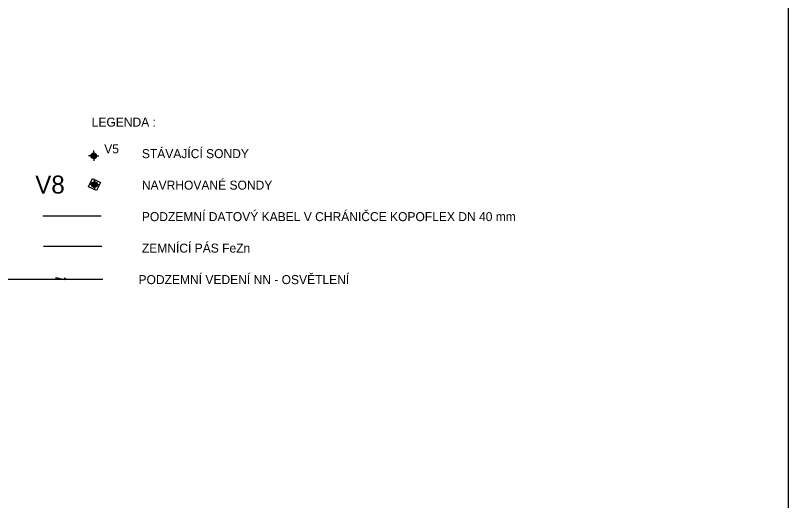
# Model space of a CAD drawing. Extents: x -517788 to -517166, y -1177087 to -1176790.
# Drawn here: x -517251.8 to -517165.9, y -1176994 to -1176940.1 of the extents above; entities that cross this region are included whole.
import ezdxf

# ---------------------------------------------------------------- set-up
doc = ezdxf.new("R2010")
doc.units = 0
doc.layers.add('mapove znacky', color=7, linetype='Continuous')
doc.layers.add('označení lomového bodu', color=7, linetype='Continuous')

msp = doc.modelspace()

# ---------------------------------------------------------------- linework, layer by layer
at = {"layer": 'mapove znacky'}
for p, q in [((-517243.399, -1176955.672), (-517243.649, -1176955.672)), ((-517243.397, -1176955.711), (-517242.898, -1176955.423)), ((-517243.396, -1176955.63), (-517242.969, -1176955.383)), ((-517243.379, -1176955.782), (-517242.846, -1176955.474)), ((-517243.365, -1176955.531), (-517243.07, -1176955.361)), ((-517243.347, -1176955.844), (-517242.808, -1176955.533)), ((-517243.302, -1176955.899), (-517242.783, -1176955.599)), ((-517243.241, -1176955.944), (-517242.774, -1176955.675)), ((-517243.157, -1176955.977), (-517242.788, -1176955.764)), ((-517243.087, -1176955.36), (-517243.087, -1176955.11)), ((-517242.774, -1176955.672), (-517242.524, -1176955.672)), ((-517243.087, -1176955.985), (-517243.087, -1176956.235)), ((-517243.017, -1176955.977), (-517242.858, -1176955.885)), ((-517243.003, -1176958.566), (-517243.003, -1176958.316)), ((-517243.315, -1176958.879), (-517243.565, -1176958.879)), ((-517243.313, -1176958.917), (-517242.814, -1176958.63)), ((-517243.312, -1176958.836), (-517242.885, -1176958.59)), ((-517243.295, -1176958.988), (-517242.762, -1176958.68)), ((-517243.281, -1176958.738), (-517242.986, -1176958.567)), ((-517243.263, -1176959.051), (-517242.724, -1176958.739)), ((-517243.218, -1176959.105), (-517242.699, -1176958.806)), ((-517243.157, -1176959.151), (-517242.69, -1176958.882)), ((-517243.073, -1176959.183), (-517242.704, -1176958.97)), ((-517243.003, -1176959.191), (-517243.003, -1176959.441)), ((-517242.933, -1176959.183), (-517242.774, -1176959.092)), ((-517242.69, -1176958.879), (-517242.44, -1176958.879))]:
    msp.add_line(p, q, dxfattribs=at)
for centre in [(-517243.087, -1176955.672), (-517243.003, -1176958.879)]:
    msp.add_circle(centre, 0.312, dxfattribs=at)
at = {"layer": 'označení lomového bodu'}
for p, q in [((-517242.277, -1176962.393), (-517248.75, -1176962.393)), ((-517242.174, -1176965.76), (-517248.647, -1176965.76)), ((-517252.874, -1176969.38), (-517242.088, -1176969.38)), ((-517247.253, -1176969.38), (-517247.253, -1176969.191)), ((-517247.253, -1176969.191), (-517246.565, -1176969.38)), ((-517246.203, -1176969.38), (-517246.378, -1176969.296)), ((-517246.203, -1176969.38), (-517246.378, -1176969.464))]:
    msp.add_line(p, q, dxfattribs=at)
for points in [[(-517375.912, -1176938.722), (-517375.912, -1177087.222), (-517165.912, -1177087.222), (-517165.912, -1176938.722)], [(-517248.647, -1176969.38), (-517248.646, -1176969.38)], [(-517248.121, -1176969.38), (-517247.253, -1176969.38)], [(-517246.565, -1176969.38), (-517246.203, -1176969.38)], [(-517245.937, -1176969.38), (-517245.153, -1176969.38)], [(-517244.67, -1176969.38), (-517243.76, -1176969.38)], [(-517243.235, -1176969.38), (-517242.318, -1176969.38)]]:
    msp.add_lwpolyline(points, dxfattribs=at)
msp.add_lwpolyline([(-517242.777, -1176959.536), (-517243.658, -1176959.113), (-517243.229, -1176958.221), (-517242.348, -1176958.644)], close=True, dxfattribs=at)

# ---------------------------------------------------------------- texts
for s, height, p in [('LEGENDA :', 1, (-517243.312, -1176952.443)), ('V5', 1, (-517241.925, -1176955.406)), ('               STÁVAJÍCÍ SONDY', 1, (-517243.312, -1176955.943)), ('V8', 2, (-517249.58, -1176959.878)), ('               NAVRHOVANÉ SONDY', 1, (-517243.312, -1176959.443)), ('               PODZEMNÍ DATOVÝ KABEL V CHRÁNIČCE KOPOFLEX DN 40 mm  ', 1, (-517243.312, -1176962.943)), ('               ZEMNÍCÍ PÁS FeZn      ', 1, (-517243.312, -1176966.443)), ('              PODZEMNÍ VEDENÍ NN - OSVĚTLENÍ', 1, (-517243.312, -1176969.943))]:
    msp.add_text(s, height=height, rotation=360, dxfattribs=at).set_placement(p)

doc.saveas('drawing.dxf')
